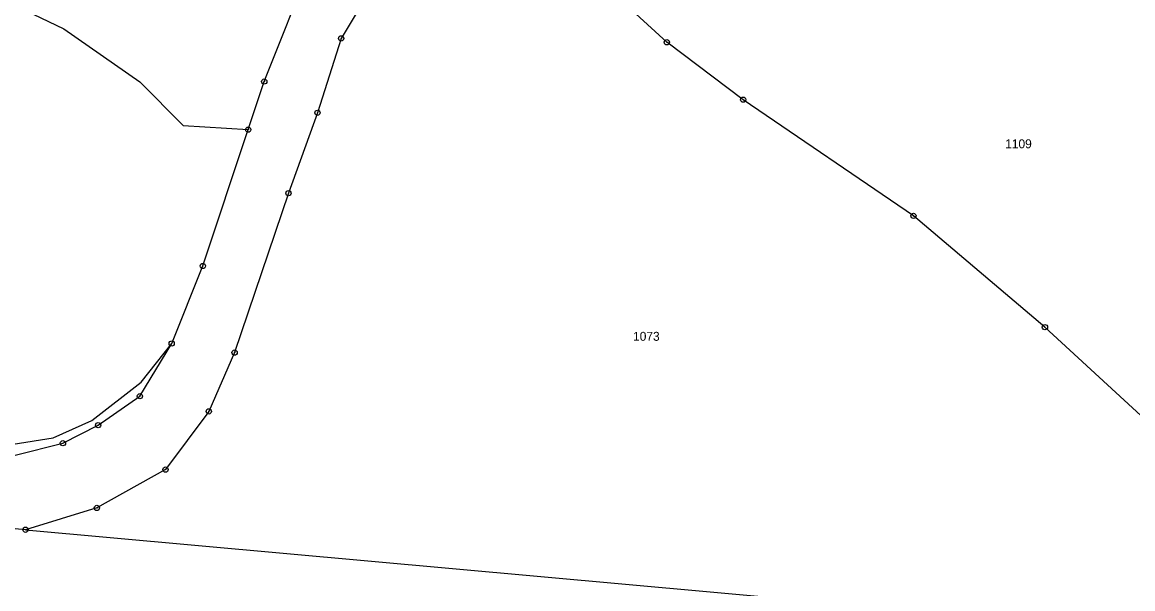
# Model space of a CAD drawing. Extents: x -758887 to -754328, y -1031688 to -1029144.
# Drawn here: x -758435 to -758223.9, y -1029435.3 to -1029327.6 of the extents above; entities that cross this region are included whole.
import ezdxf
from ezdxf.enums import TextEntityAlignment as Align

# ---------------------------------------------------------------- set-up
doc = ezdxf.new("R2010")
doc.units = 0
doc.header["$LTSCALE"] = 0.68
doc.layers.add('1', color=7, linetype='Continuous', lineweight=25)
doc.layers.add('8', color=7, linetype='Continuous', lineweight=25)
doc.layers.add('2', color=7, linetype='Continuous')

msp = doc.modelspace()

# ---------------------------------------------------------------- linework, layer by layer
at = {"layer": '1'}
for points in [[(-758392.05, -1029348.07), (-758389, -1029338.93), (-758379.94, -1029316.17), (-758372.88, -1029305.78), (-758364.21, -1029298.46), (-758346.08, -1029289.22)], [(-758340.67, -1029300.89), (-758347.87, -1029303.9), (-758366.2, -1029317.5), (-758368.71, -1029321.17), (-758374.39, -1029330.73), (-758378.89, -1029344.86), (-758384.41, -1029360.14), (-758394.64, -1029390.44), (-758399.55, -1029401.61), (-758407.78, -1029412.68), (-758420.82, -1029419.96), (-758434.38, -1029424.1)], [(-758190.92, -1029431.64), (-758198.56, -1029424.31), (-758240.61, -1029385.61), (-758265.6, -1029364.46), (-758297.96, -1029342.37), (-758312.48, -1029331.46), (-758327.18, -1029317.95), (-758340.67, -1029300.89)], [(-758454.59, -1029315.76), (-758427.08, -1029328.92), (-758412.67, -1029338.97), (-758404.39, -1029347.29), (-758392.05, -1029348.07)], [(-758406.6, -1029388.71), (-758400.68, -1029373.98), (-758392.05, -1029348.07)], [(-758876.17, -1029350.61), (-758872.04, -1029354.94), (-758867.03, -1029356.46), (-758737.18, -1029373.09), (-758669.17, -1029381.61), (-758589.35, -1029390.89), (-758518.53, -1029400.82), (-758473.41, -1029407.66), (-758450.9, -1029410.38), (-758436.36, -1029409.91), (-758427.27, -1029407.66), (-758420.59, -1029404.23), (-758412.65, -1029398.73), (-758406.6, -1029388.71)], [(-758837.95, -1029357.1), (-758837.26, -1029357.18), (-758803.09, -1029362.25), (-758770.49, -1029366.4), (-758737.29, -1029370.89), (-758703.46, -1029375.15), (-758669.37, -1029378.99), (-758631.59, -1029383.16), (-758589.33, -1029388.17), (-758551.96, -1029392.92), (-758517.28, -1029398.2), (-758482.61, -1029403.35), (-758459.21, -1029406.64), (-758449.44, -1029407.81), (-758436.76, -1029407.83), (-758429.11, -1029406.62), (-758421.76, -1029403.35), (-758412.4, -1029396.06), (-758406.6, -1029388.71)], [(-758434.38, -1029424.1), (-758459.22, -1029421.73), (-758465.35, -1029420.59), (-758499.63, -1029415.71), (-758546.9, -1029409.94), (-758596.65, -1029403.58), (-758628.38, -1029399.43), (-758652.79, -1029397.45), (-758691.65, -1029390.95), (-758706.46, -1029388.73), (-758731.24, -1029385.5), (-758752.58, -1029383.1), (-758778.82, -1029383.44), (-758795.46, -1029382.32), (-758811.39, -1029378.56), (-758824.75, -1029372.42), (-758837.03, -1029368.67), (-758840, -1029368.31)], [(-758434.38, -1029424.1), (-758304.27, -1029435.91), (-758174.15, -1029447.73), (-758190.92, -1029431.64)]]:
    msp.add_lwpolyline(points, dxfattribs=at)
at = {"layer": '8'}
for centre, radius in [((-758374.39, -1029330.7299), 0.5), ((-758374.39, -1029330.7299), 0.0303), ((-758312.48, -1029331.4599), 0.5), ((-758312.48, -1029331.4599), 0.0303), ((-758389, -1029338.9299), 0.5), ((-758389, -1029338.9299), 0.0303), ((-758297.96, -1029342.3699), 0.5), ((-758297.96, -1029342.3699), 0.0303), ((-758378.89, -1029344.8599), 0.5), ((-758378.89, -1029344.8599), 0.0303), ((-758392.05, -1029348.0699), 0.5), ((-758392.05, -1029348.0699), 0.0303), ((-758384.41, -1029360.1399), 0.5), ((-758384.41, -1029360.1399), 0.0303), ((-758265.6, -1029364.4599), 0.5), ((-758265.6, -1029364.4599), 0.0303), ((-758400.68, -1029373.9799), 0.5), ((-758400.68, -1029373.9799), 0.0303), ((-758240.61, -1029385.6099), 0.5), ((-758240.61, -1029385.6099), 0.0303), ((-758406.6, -1029388.7099), 0.5), ((-758406.6, -1029388.7099), 0.0303), ((-758394.64, -1029390.4399), 0.5), ((-758394.64, -1029390.4399), 0.0303), ((-758412.65, -1029398.7299), 0.5), ((-758412.65, -1029398.7299), 0.0303), ((-758399.55, -1029401.6099), 0.5), ((-758399.55, -1029401.6099), 0.0303), ((-758420.59, -1029404.2299), 0.5), ((-758420.59, -1029404.2299), 0.0303), ((-758427.27, -1029407.6599), 0.5), ((-758427.27, -1029407.6599), 0.0303), ((-758407.78, -1029412.6799), 0.5), ((-758407.78, -1029412.6799), 0.0303), ((-758420.82, -1029419.9599), 0.5), ((-758420.82, -1029419.9599), 0.0303), ((-758434.38, -1029424.0999), 0.5), ((-758434.38, -1029424.0999), 0.0303)]:
    msp.add_circle(centre, radius, dxfattribs=at)

# ---------------------------------------------------------------- texts
at = {"layer": '2'}
for s, p in [('1109', (-758245.64, -1029351.606)), ('1073', (-758316.37, -1029388.196))]:
    msp.add_text(s, height=1.7, dxfattribs=at).set_placement(p, align=Align.CENTER)

doc.saveas('drawing.dxf')
